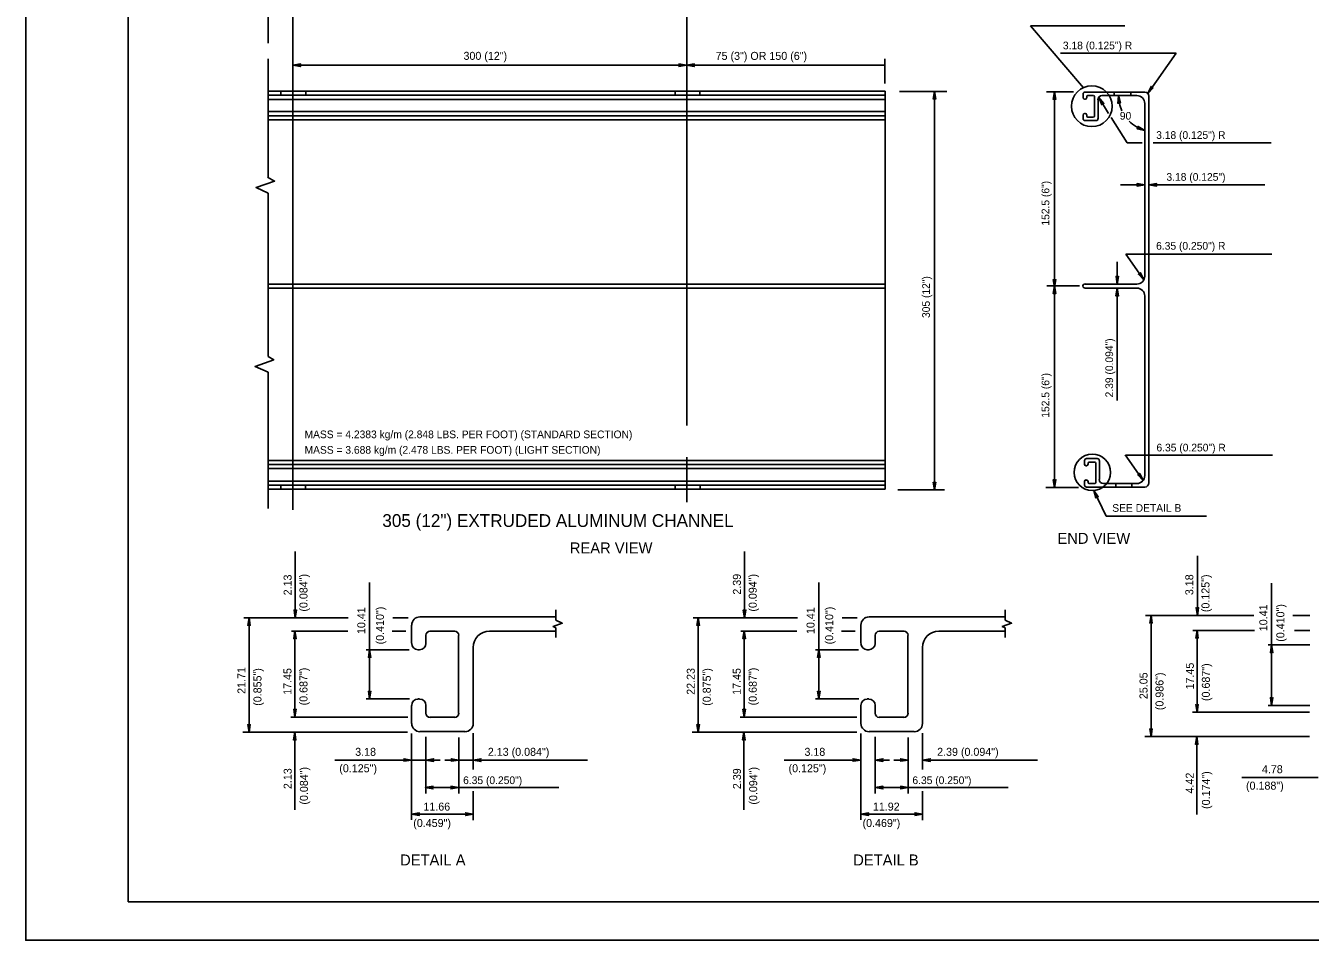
# Model space of a CAD drawing. Extents: x 647822 to 648727, y 298458 to 299646.
# Drawn here: x 647822 to 648324, y 298458 to 298815 of the extents above; entities that cross this region are included whole.
import ezdxf

# ---------------------------------------------------------------- set-up
doc = ezdxf.new("R2010")
doc.units = 0
for name, color, linetype in [('1', 7, 'Continuous'), ('2', 7, 'Continuous'), ('3', 7, 'Continuous'), ('XCS-GRID-MIN', 7, 'Continuous')]:
    doc.layers.add(name, color=color, linetype=linetype)

# ---------------------------------------------------------------- blocks, each defined once
blk = doc.blocks.new('RARROW')
at = {"layer": '3'}
blk.add_lwpolyline([(-2.2695, 0.285), (-2.184875, 0.12075), (0, 0), (-2.2695, 0.285), (-2.38575, 0.384625), (0, 0), (-2.183125, -0.108), (-2.262875, -0.2705), (0, 0), (-2.38575, -0.379125), (-2.262875, -0.2705)], dxfattribs=at)

msp = doc.modelspace()

# ---------------------------------------------------------------- linework, layer by layer
at = {"layer": '1'}
for p, q in [((647862.31, 299036.63), (647862.31, 298472.63)), ((648648.31, 298472.63), (647862.31, 298472.63)), ((647862.31, 298472.63), (648448.31, 298472.63))]:
    msp.add_line(p, q, dxfattribs=at)
at = {"layer": '2'}
for p, q in [((647926.69, 298625.88), (647926.69, 298836.63)), ((648080.56, 298836.63), (648080.56, 298658.79)), ((647917.06, 298826.5), (647917.06, 298808.25)), ((648214.75, 298815.06), (648235.45, 298790.86)), ((648251.69, 298815.06), (648214.75, 298815.06)), ((648271.68, 298804.33), (648226.51, 298804.33)), ((648260.57, 298788.63), (648271.68, 298804.33)), ((647917.06, 298802.13), (647917.06, 298755.75)), ((648080.44, 298799.63), (647926.69, 298799.63)), ((648157.94, 298799.63), (648080.44, 298799.63)), ((648157.94, 298792.5), (648157.94, 298802.13)), ((648158.06, 298789.5), (647917.06, 298789.5)), ((647921.94, 298787.88), (647921.94, 298789.5)), ((647931.69, 298787.88), (647931.69, 298789.5)), ((648075.94, 298787.88), (648075.94, 298789.5)), ((648085.69, 298787.88), (648085.69, 298789.5)), ((648158.06, 298789.5), (648158.06, 298634)), ((648182.06, 298789.38), (648163.69, 298789.38)), ((648177.31, 298633.63), (648177.31, 298789.38)), ((648231.57, 298789.25), (648221.07, 298789.25)), ((648224.19, 298712.88), (648224.19, 298789.25)), ((648236.19, 298789.13), (648259.44, 298789.13)), ((648247.44, 298789.13), (648247.44, 298787.75)), ((648253.94, 298787.75), (648253.94, 298789.13)), ((648158.06, 298787.88), (647917.06, 298787.88)), ((648158.06, 298786.25), (647917.06, 298786.25)), ((648235.32, 298787), (648235.32, 298788.38)), ((648236.19, 298786.38), (648235.94, 298786.38)), ((648236.82, 298787.38), (648236.82, 298787)), ((648239.32, 298787.75), (648237.19, 298787.75)), ((648239.82, 298779.75), (648239.82, 298787.38)), ((648241.19, 298786.13), (648241.19, 298778.75)), ((648241.44, 298787), (648245.32, 298780.77)), ((648256.32, 298787.75), (648242.69, 298787.75)), ((648259.44, 298717.25), (648259.44, 298784.63)), ((648261.07, 298787.5), (648261.07, 298636.38)), ((648158.06, 298781.5), (647917.06, 298781.5)), ((648158.06, 298779.88), (647917.06, 298779.88)), ((648235.32, 298778.75), (648235.32, 298780.13)), ((648235.94, 298780.75), (648236.19, 298780.75)), ((648236.82, 298780.13), (648236.82, 298779.75)), ((648237.19, 298779.38), (648239.32, 298779.38)), ((648246.32, 298779.25), (648252.57, 298769.25)), ((648158.06, 298778.25), (647917.06, 298778.25)), ((648240.32, 298778), (648236.19, 298778)), ((648258.37, 298769.25), (648252.57, 298769.25)), ((648308.85, 298769.25), (648262.72, 298769.25)), ((647917.06, 298749.63), (647917.06, 298685.75)), ((648259.44, 298752.88), (648249.94, 298752.88)), ((648306.27, 298752.88), (648261.07, 298752.88)), ((648259.07, 298715.75), (648252.07, 298725.75)), ((648309.09, 298725.75), (648252.07, 298725.75)), ((648248.69, 298714.13), (648248.69, 298722.75)), ((648158.06, 298714.13), (647917.06, 298714.13)), ((648236.19, 298714.13), (648256.32, 298714.13)), ((648158.06, 298712.5), (647917.06, 298712.5)), ((648233.94, 298713.38), (648221.19, 298713.38)), ((648224.19, 298634.63), (648224.19, 298713.38)), ((648256.32, 298712.5), (648236.19, 298712.5)), ((648248.69, 298668.64), (648248.69, 298712.5)), ((648259.44, 298639.25), (648259.44, 298709.5)), ((647917.06, 298679.63), (647917.06, 298626.38)), ((648158.06, 298645.13), (647917.06, 298645.13)), ((648158.06, 298643.63), (647917.06, 298643.63)), ((648080.56, 298646.52), (648080.56, 298628.93)), ((648235.94, 298643.75), (648235.94, 298645.13)), ((648236.69, 298645.88), (648240.94, 298645.88)), ((648237.32, 298644.13), (648237.32, 298643.75)), ((648239.94, 298644.5), (648237.69, 298644.5)), ((648240.32, 298636.5), (648240.32, 298644.13)), ((648241.69, 298645.13), (648241.69, 298637.75)), ((648258.82, 298637.38), (648251.82, 298647.38)), ((648309.33, 298647.25), (648252.07, 298647.25)), ((648158.06, 298642), (647917.06, 298642)), ((648236.69, 298643.13), (648236.44, 298643.13)), ((648158.06, 298637.13), (647917.06, 298637.13)), ((648158.06, 298635.5), (647917.06, 298635.5)), ((648158.06, 298634), (647917.06, 298634)), ((647921.94, 298634), (647921.94, 298635.5)), ((647931.56, 298634), (647931.56, 298635.5)), ((648076.06, 298634), (648076.06, 298635.63)), ((648085.81, 298634), (648085.81, 298635.5)), ((648181.19, 298633.63), (648162.94, 298633.63)), ((648233.57, 298634.63), (648220.82, 298634.63)), ((648235.94, 298635.5), (648235.94, 298637)), ((648236.44, 298637.5), (648236.69, 298637.5)), ((648259.44, 298634.75), (648236.69, 298634.75)), ((648237.32, 298637), (648237.32, 298636.5)), ((648237.69, 298636.13), (648239.94, 298636.13)), ((648243.32, 298636.13), (648256.32, 298636.13)), ((648248.07, 298636.13), (648248.07, 298634.75)), ((648254.44, 298634.75), (648254.44, 298636.13)), ((648244.32, 298623.38), (648239.47, 298633.45)), ((648283.53, 298623.38), (648244.32, 298623.38)), ((647927.63, 298583.7), (647927.63, 298609.61)), ((648103.11, 298583.7), (648103.11, 298609.61)), ((648279.97, 298584.63), (648279.97, 298607.91)), ((647956.66, 298551.95), (647956.66, 298597.51)), ((648132.14, 298551.95), (648132.14, 298597.51)), ((648308.99, 298549.42), (648308.99, 298597.15)), ((647948.27, 298583.7), (647907.54, 298583.7)), ((647909.54, 298538.95), (647909.54, 298583.7)), ((647971.66, 298583.7), (647965.7, 298583.7)), ((648029.41, 298584.07), (647976.29, 298584.07)), ((648029.41, 298582.7), (648029.41, 298586.82)), ((648123.75, 298583.7), (648083.02, 298583.7)), ((648085.02, 298538.95), (648085.02, 298583.7)), ((648147.15, 298583.7), (648141.18, 298583.7)), ((648204.9, 298584.07), (648151.77, 298584.07)), ((648204.9, 298582.7), (648204.9, 298586.82)), ((648302.05, 298584.63), (648259.77, 298584.63)), ((648261.88, 298537.25), (648261.88, 298584.63)), ((648323.9, 298584.63), (648317.25, 298584.63)), ((647948.09, 298578.45), (647926.13, 298578.45)), ((647927.5, 298544.95), (647927.5, 298578.57)), ((647970.79, 298578.45), (647965.52, 298578.45)), ((647973.04, 298580.82), (647973.04, 298573.7)), ((647989.91, 298578.45), (647980.16, 298578.45)), ((648029.41, 298578.45), (648003.54, 298578.45)), ((648029.41, 298575.95), (648029.41, 298579.7)), ((648123.58, 298578.45), (648101.61, 298578.45)), ((648102.99, 298544.95), (648102.99, 298578.57)), ((648146.27, 298578.45), (648141, 298578.45)), ((648148.52, 298580.82), (648148.52, 298573.7)), ((648165.4, 298578.45), (648155.65, 298578.45)), ((648204.9, 298578.45), (648179.02, 298578.45)), ((648204.9, 298575.95), (648204.9, 298579.7)), ((648278.19, 298578.75), (648302.29, 298578.75)), ((648279.84, 298546.75), (648279.84, 298578.75)), ((648317.96, 298578.75), (648323.9, 298578.75)), ((647978.66, 298576.82), (647978.66, 298573.7)), ((647991.41, 298546.32), (647991.41, 298576.82)), ((648154.15, 298576.82), (648154.15, 298573.7)), ((648166.9, 298546.32), (648166.9, 298576.82)), ((647972.16, 298571.2), (647955.28, 298571.2)), ((647976.16, 298571.2), (647975.54, 298571.2)), ((647997.16, 298542.32), (647997.16, 298572.07)), ((648147.65, 298571.2), (648130.77, 298571.2)), ((648151.65, 298571.2), (648151.02, 298571.2)), ((648172.65, 298542.32), (648172.65, 298572.07)), ((648323.97, 298573.05), (648307.69, 298573.05)), ((647972.29, 298551.95), (647955.28, 298551.95)), ((647973.04, 298549.45), (647973.04, 298542.32)), ((647976.16, 298551.95), (647975.54, 298551.95)), ((647978.66, 298549.45), (647978.66, 298546.32)), ((648147.77, 298551.95), (648130.77, 298551.95)), ((648148.52, 298549.45), (648148.52, 298542.32)), ((648151.65, 298551.95), (648151.02, 298551.95)), ((648154.15, 298549.45), (648154.15, 298546.32)), ((648323.9, 298549.42), (648307.62, 298549.42)), ((647971.54, 298544.82), (647925.88, 298544.82)), ((647980.16, 298544.82), (647989.91, 298544.82)), ((648147.02, 298544.82), (648101.36, 298544.82)), ((648155.65, 298544.82), (648165.4, 298544.82)), ((648323.74, 298546.75), (648278.08, 298546.75)), ((647971.41, 298538.95), (647907.16, 298538.95)), ((647927.38, 298508.56), (647927.38, 298538.95)), ((647973.04, 298504.7), (647973.04, 298538.45)), ((647976.29, 298539.2), (647993.91, 298539.2)), ((647997.16, 298524.45), (647997.16, 298538.57)), ((648146.9, 298538.95), (648082.65, 298538.95)), ((648102.86, 298508.56), (648102.86, 298538.95)), ((648148.52, 298504.7), (648148.52, 298538.45)), ((648151.77, 298539.2), (648169.4, 298539.2)), ((648172.65, 298524.45), (648172.65, 298538.57)), ((647978.66, 298515.07), (647978.66, 298537.2)), ((647991.54, 298515.07), (647991.54, 298536.95)), ((648154.15, 298515.07), (648154.15, 298537.2)), ((648167.02, 298515.07), (648167.02, 298536.95)), ((648323.75, 298537.25), (648259.5, 298537.25)), ((648279.72, 298506.86), (648279.72, 298537.25)), ((647973.04, 298528.08), (647943.12, 298528.08)), ((647978.66, 298528.08), (647973.04, 298528.08)), ((647984.18, 298528.08), (647978.66, 298528.08)), ((647991.54, 298528.08), (647985.97, 298528.08)), ((647997.16, 298528.08), (647991.54, 298528.08)), ((648041.8, 298528.08), (647997.16, 298528.08)), ((648148.52, 298528.08), (648118.61, 298528.08)), ((648159.66, 298528.08), (648154.15, 298528.08)), ((648167.02, 298528.08), (648161.45, 298528.08)), ((648217.48, 298528.08), (648172.65, 298528.08)), ((648327.21, 298521.29), (648297.29, 298521.29)), ((647973.04, 298517.07), (647973.04, 298516.95)), ((648030.6, 298517.32), (647978.41, 298517.32)), ((647997.16, 298504.57), (647997.16, 298515.91)), ((648148.52, 298517.07), (648148.52, 298516.95)), ((648206.09, 298517.32), (648154.15, 298517.32)), ((648172.65, 298504.57), (648172.65, 298515.91)), ((647997.16, 298506.95), (647973.04, 298506.95)), ((648172.65, 298506.95), (648148.52, 298506.95))]:
    msp.add_line(p, q, dxfattribs=at)
for points in [[(647917.06, 298749.63), (647912.31, 298751.88), (647919.56, 298754.38), (647916.81, 298755.88)], [(647917.06, 298679.63), (647911.94, 298681.88), (647919.19, 298684.5), (647917.06, 298685.75)], [(648029.41, 298579.7), (648028.29, 298580.32), (648031.91, 298581.57), (648029.41, 298582.7)], [(648204.9, 298579.7), (648203.77, 298580.32), (648207.4, 298581.57), (648204.9, 298582.7)]]:
    msp.add_lwpolyline(points, dxfattribs=at)
for centre, radius in [((648238.75, 298783.61), 7.97), ((648238.93, 298640.52), 7.09)]:
    msp.add_circle(centre, radius, dxfattribs=at)
for centre, radius, start, end in [((648236.15, 298788.35), 0.795, 90, 180), ((648259.42, 298787.55), 1.6, 0, 90), ((648235.97, 298786.96), 0.612, 180, 270), ((648236.15, 298786.96), 0.612, 270, 0), ((648237.16, 298787.35), 0.398, 90, 180), ((648239.35, 298787.35), 0.398, 0, 90), ((648242.74, 298786.16), 1.59, 90, 180), ((648263.38, 298787.81), 14.21, 180.1857, 204.9016), ((648256.35, 298784.69), 3.08, 0, 90), ((648235.97, 298780.17), 0.612, 90, 180), ((648236.15, 298780.17), 0.612, 0, 90), ((648237.16, 298779.78), 0.398, 180, 270), ((648239.35, 298779.78), 0.398, 270, 0), ((648236.15, 298778.78), 0.795, 180, 270), ((648240.35, 298778.78), 0.795, 270, 0), ((648263.38, 298787.81), 14.21, 225.0505, 253.8315), ((648236.08, 298713.35), 0.818, 78.8792, 275.6682), ((648256.32, 298717.2), 3.08, 270, 0), ((648256.35, 298709.46), 3.08, 0, 90), ((648236.69, 298645.12), 0.795, 90, 180), ((648236.5, 298643.73), 0.612, 180, 270), ((648236.69, 298643.73), 0.612, 270, 0), ((648237.7, 298644.12), 0.398, 90, 180), ((648239.89, 298644.12), 0.398, 0, 90), ((648240.88, 298645.12), 0.795, 0, 90), ((648256.35, 298639.23), 3.08, 270, 0), ((648236.5, 298636.94), 0.612, 90, 180), ((648236.69, 298635.55), 0.795, 180, 270), ((648236.69, 298636.94), 0.612, 0, 90), ((648237.7, 298636.54), 0.398, 180, 270), ((648239.89, 298636.54), 0.398, 270, 0), ((648243.27, 298637.74), 1.59, 180, 270), ((648259.42, 298636.36), 1.6, 270, 0), ((647976.3, 298580.83), 3.2, 90.3673, 180), ((648151.78, 298580.83), 3.2, 90.3673, 180), ((647980.24, 298576.84), 1.6, 90, 180), ((647989.86, 298576.84), 1.6, 0, 90), ((648003.51, 298572.04), 6.4, 90, 180), ((648155.72, 298576.84), 1.6, 90, 180), ((648165.35, 298576.84), 1.6, 0, 90), ((648178.99, 298572.04), 6.4, 90, 180), ((647975.56, 298573.67), 2.46, 180, 270), ((647976.17, 298573.67), 2.46, 270, 0), ((648151.04, 298573.67), 2.46, 180, 270), ((648151.66, 298573.67), 2.46, 270, 0), ((647975.56, 298549.46), 2.46, 90, 180), ((647976.17, 298549.46), 2.46, 0, 90), ((648151.04, 298549.46), 2.46, 90, 180), ((648151.66, 298549.46), 2.46, 0, 90), ((647980.24, 298546.36), 1.6, 180, 270), ((647989.86, 298546.36), 1.6, 270, 0), ((648155.72, 298546.36), 1.6, 180, 270), ((648165.35, 298546.36), 1.6, 270, 0), ((647976.3, 298542.35), 3.2, 180, 270), ((647993.9, 298542.35), 3.2, 270, 0), ((648151.78, 298542.35), 3.2, 180, 270), ((648169.39, 298542.35), 3.2, 270, 0)]:
    msp.add_arc(centre, radius, start, end, dxfattribs=at)
at = {"layer": 'XCS-GRID-MIN'}
msp.add_lwpolyline([(647822.31, 299051.63), (648663.31, 299051.63), (648663.31, 298457.63), (647822.31, 298457.63)], close=True, dxfattribs=at)

# ---------------------------------------------------------------- block references
at = {"layer": '2'}
for p, xscale, yscale, rotation in [((647926.69, 298799.63), 1.2574347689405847, 1.3092961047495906, 180), ((648080.44, 298799.63), 1.2574347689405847, 1.3092961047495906, 180), ((648177.31, 298789.38), 1.2574347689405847, 1.3092961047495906, 89.99999999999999), ((648224.19, 298789.25), 1.2574347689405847, 1.3092961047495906, 89.99999999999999), ((648260.57, 298788.63), 1.2574347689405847, 1.3092961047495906, -125.1874600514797), ((648241.44, 298787), 1.2574347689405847, 1.3092961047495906, 121.93643129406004), ((648249.17, 298787.76), 1.2574347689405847, 1.3092961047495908, 95.3085792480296), ((648259.42, 298774.16), 1.257434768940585, 1.3092961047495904, -21.314522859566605), ((648261.07, 298752.88), 1.2574347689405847, 1.3092961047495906, 180), ((648224.19, 298712.88), 1.2574347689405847, 1.3092961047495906, -90.00000000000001), ((648248.69, 298714.13), 1.2574347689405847, 1.3092961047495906, -90.00000000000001), ((648259.07, 298715.75), 1.2574347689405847, 1.3092961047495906, -55.4952507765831), ((648224.19, 298713.38), 1.2574347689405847, 1.3092961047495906, 89.99999999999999), ((648248.69, 298712.5), 1.2574347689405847, 1.3092961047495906, 89.99999999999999), ((648258.82, 298637.38), 1.2574347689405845, 1.3092961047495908, -54.53715823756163), ((648177.31, 298633.63), 1.2574347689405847, 1.3092961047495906, -90.00000000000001), ((648224.19, 298634.63), 1.2574347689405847, 1.3092961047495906, -90.00000000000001), ((648239.47, 298633.45), 1.2574347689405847, 1.3092961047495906, 116.22067749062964), ((647909.54, 298583.7), 1.2574347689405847, 1.3092961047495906, 89.99999999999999), ((647927.63, 298583.7), 1.2574347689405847, 1.3092961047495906, -90.00000000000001), ((648085.02, 298583.7), 1.2574347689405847, 1.3092961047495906, 89.99999999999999), ((648103.11, 298583.7), 1.2574347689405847, 1.3092961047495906, -90.00000000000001), ((648261.88, 298584.63), 1.2574347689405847, 1.3092961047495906, 89.99999999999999), ((648279.97, 298584.63), 1.2574347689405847, 1.3092961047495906, -90.00000000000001), ((647927.5, 298578.57), 1.2574347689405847, 1.3092961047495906, 89.99999999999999), ((648102.99, 298578.57), 1.2574347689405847, 1.3092961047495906, 89.99999999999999), ((648279.84, 298578.75), 1.2574347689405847, 1.3092961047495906, 89.99999999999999), ((647956.66, 298571.2), 1.2574347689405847, 1.3092961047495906, 89.99999999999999), ((648132.14, 298571.2), 1.2574347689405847, 1.3092961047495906, 89.99999999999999), ((648308.99, 298573.05), 1.2574347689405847, 1.3092961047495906, 89.99999999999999), ((647956.66, 298551.95), 1.2574347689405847, 1.3092961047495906, -90.00000000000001), ((648132.14, 298551.95), 1.2574347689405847, 1.3092961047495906, -90.00000000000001), ((648279.84, 298546.75), 1.2574347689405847, 1.3092961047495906, -90.00000000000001), ((648308.99, 298549.42), 1.2574347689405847, 1.3092961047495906, -90.00000000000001), ((647927.5, 298544.95), 1.2574347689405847, 1.3092961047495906, -90.00000000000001), ((648102.99, 298544.95), 1.2574347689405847, 1.3092961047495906, -90.00000000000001), ((647909.54, 298538.95), 1.2574347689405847, 1.3092961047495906, -90.00000000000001), ((647927.38, 298538.95), 1.2574347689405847, 1.3092961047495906, 89.99999999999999), ((648085.02, 298538.95), 1.2574347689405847, 1.3092961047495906, -90.00000000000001), ((648102.86, 298538.95), 1.2574347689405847, 1.3092961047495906, 89.99999999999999), ((648261.88, 298537.25), 1.2574347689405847, 1.3092961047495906, -90.00000000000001), ((648279.72, 298537.25), 1.2574347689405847, 1.3092961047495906, 89.99999999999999), ((647978.66, 298528.08), 1.2574347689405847, 1.3092961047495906, 180), ((647997.16, 298528.08), 1.2574347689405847, 1.3092961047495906, 180), ((648154.15, 298528.08), 1.2574347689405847, 1.3092961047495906, 180), ((648172.65, 298528.08), 1.2574347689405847, 1.3092961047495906, 180), ((647978.41, 298517.32), 1.2574347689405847, 1.3092961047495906, 180), ((648154.15, 298517.32), 1.2574347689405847, 1.3092961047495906, 180), ((647973.04, 298506.95), 1.2574347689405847, 1.3092961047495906, 180), ((648148.52, 298506.95), 1.2574347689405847, 1.3092961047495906, 180)]:
    msp.add_blockref('RARROW', p, dxfattribs=dict(at, xscale=xscale, yscale=yscale, rotation=rotation))
at = {"layer": '2', "xscale": 1.2574347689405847, "yscale": 1.3092961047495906}
for p in [(648080.44, 298799.63), (648259.44, 298752.88), (647973.04, 298528.08), (647991.54, 298528.08), (648148.52, 298528.08), (648167.02, 298528.08), (647991.41, 298517.32), (648167.02, 298517.32), (647997.16, 298506.95), (648172.65, 298506.95)]:
    msp.add_blockref('RARROW', p, dxfattribs=at)

# ---------------------------------------------------------------- texts
at = {"layer": '2'}
for s, height, p in [('300 (12")', 3.125, (647993.32, 298801.74)), ('75 (3") OR 150 (6")', 3.1252, (648091.81, 298801.72)), ('3.18 (0.125") R', 3, (648227.45, 298805.86)), ('90', 3, (648249.69, 298778.38)), ('3.18 (0.125") R', 3, (648263.89, 298770.85)), ('3.18 (0.125")', 3, (648267.9, 298754.48)), ('6.35 (0.250") R', 3, (648263.87, 298727.55)), ('MASS = 4.2383 kg/m (2.848 LBS. PER FOOT) (STANDARD SECTION)', 3, (647931.22, 298653.87)), ('MASS = 3.688 kg/m (2.478 LBS. PER FOOT) (LIGHT SECTION)', 3, (647931.24, 298647.8)), ('6.35 (0.250") R', 3, (648264, 298648.7)), ('305 (12") EXTRUDED ALUMINUM CHANNEL', 5, (647961.61, 298619.18)), ('SEE DETAIL B', 3, (648246.73, 298625.1)), ('END VIEW', 4.3, (648225.32, 298612.58)), ('REAR VIEW', 4.3, (648034.85, 298608.83)), ('3.18', 3.125, (647951.02, 298529.73)), ('2.13 (0.084")', 3.1252, (648002.83, 298529.73)), ('3.18', 3.125, (648126.5, 298529.73)), ('2.39 (0.094")', 3.1252, (648178.32, 298529.73)), ('(0.125")', 3.125, (647944.81, 298523.31)), ('(0.125")', 3.125, (648120.29, 298523.31)), ('4.78', 3.125, (648305.19, 298522.94)), ('6.35 (0.250")', 3, (647993.18, 298518.69)), ('6.35 (0.250")', 3, (648168.67, 298518.69)), ('(0.188")', 3.125, (648298.98, 298516.51)), ('11.66', 3.125, (647977.66, 298508.32)), ('11.92', 3.125, (648153.23, 298508.32)), ('(0.459")', 3.125, (647973.7, 298501.92)), ('(0.469")', 3.125, (648149.19, 298501.92)), ('DETAIL A', 4.3, (647968.56, 298486.88)), ('DETAIL B', 4.3, (648145.56, 298486.88))]:
    msp.add_text(s, height=height, dxfattribs=at).set_placement(p)
for s, height, p in [('152.5 (6")', 3, (648222.15, 298736.95)), ('305 (12")', 3, (648175.5, 298700.84)), ('2.39 (0.094")', 3, (648247.05, 298669.82)), ('152.5 (6")', 3, (648222.15, 298661.88)), ('2.13 ', 3.125, (647926.18, 298592.44)), ('(0.084")', 3.125, (647932.38, 298586.1)), ('2.39', 3.125, (648101.67, 298592.72)), ('(0.094")', 3.125, (648107.86, 298586.1)), ('3.18', 3.125, (648278.38, 298592.53)), ('(0.125")', 3.125, (648284.71, 298585.89)), ('10.41', 3.125, (648307.3, 298578.43)), ('(0.410")', 3.125, (648313.96, 298574.31)), ('10.41', 3.125, (647954.96, 298577.34)), ('(0.410")', 3.125, (647962.25, 298573.29)), ('10.41', 3.125, (648130.44, 298577.34)), ('(0.410")', 3.125, (648137.73, 298573.29)), ('21.71', 3.125, (647908.16, 298553.95)), ('(0.855")', 3.125, (647914.41, 298549.28)), ('17.45', 3.125, (647926.13, 298553.57)), ('(0.687")', 3.125, (647932.38, 298549.45)), ('22.23', 3.125, (648083.65, 298553.59)), ('(0.875")', 3.125, (648089.9, 298549.28)), ('17.45', 3.125, (648101.61, 298553.57)), ('(0.687")', 3.125, (648107.86, 298549.45)), ('17.45', 3.125, (648278.6, 298555.67)), ('(0.687")', 3.125, (648284.85, 298551.15)), ('25.05', 3.125, (648260.5, 298551.89)), ('(0.986")', 3.125, (648266.75, 298547.58)), ('2.13', 3.125, (647926.21, 298516.73)), ('(0.084")', 3.125, (647932.55, 298510.67)), ('2.39', 3.125, (648101.7, 298516.72)), ('(0.094")', 3.125, (648108.04, 298510.67)), ('(0.174")', 3.125, (648284.89, 298508.98)), ('4.42', 3.125, (648278.55, 298515.03))]:
    msp.add_text(s, height=height, rotation=90, dxfattribs=at).set_placement(p)

doc.saveas('drawing.dxf')
